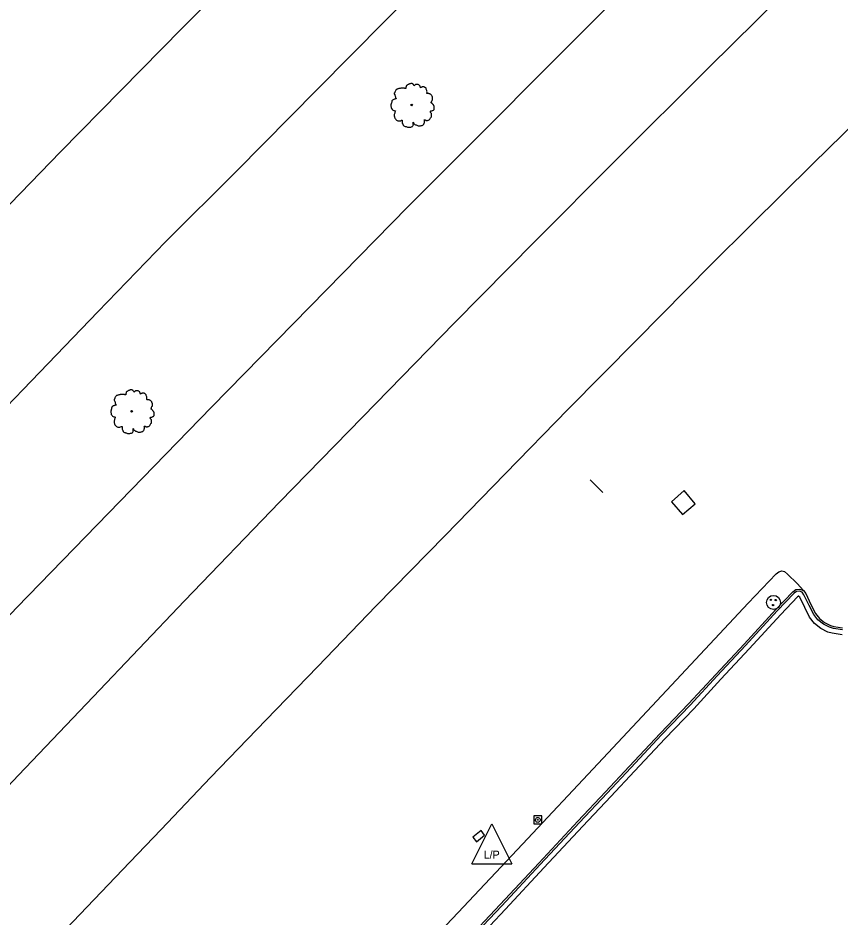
# Model space of a CAD drawing. Extents: x 2161152 to 2175754, y 602179 to 617749.
# Drawn here: x 2163328.7 to 2163534.2, y 605404.6 to 605629.5 of the extents above; entities that cross this region are included whole.
import ezdxf

# ---------------------------------------------------------------- set-up
doc = ezdxf.new("R2010")
doc.units = 0
for name, color, linetype in [('RD_EX_BldgApp_Sign', 7, 'Continuous'), ('RD_EX_Conc_Curb', 7, 'Continuous'), ('RD_EX_Conc_Gutter', 7, 'Continuous'), ('RD_EX_Conc_Sidewalk', 7, 'Continuous'), ('RD_EX_DR_Inlet', 7, 'Continuous'), ('RD_EX_Fence_Other', 7, 'Continuous'), ('RD_EX_Misc', 7, 'Continuous'), ('RD_EX_Road', 7, 'Continuous'), ('RD_EX_UT', 7, 'Continuous'), ('RD_EX_VEG', 7, 'Continuous')]:
    doc.layers.add(name, color=color, linetype=linetype)

msp = doc.modelspace()

# ---------------------------------------------------------------- linework, layer by layer
at = {"layer": 'RD_EX_BldgApp_Sign'}
msp.add_line((2163474.9, 605510.92), (2163471.74, 605514.08), dxfattribs=at)
at = {"layer": 'RD_EX_Conc_Curb'}
for points in [[(2163441.47, 605399.73), (2163449.26, 605408.02), (2163458.9, 605418.35), (2163468.67, 605428.78), (2163475.61, 605436.15), (2163481.51, 605442.46), (2163489.25, 605450.68), (2163496.34, 605458.1), (2163503.15, 605465.43), (2163510.21, 605473.01), (2163518.13, 605481.66), (2163522.37, 605486.12), (2163523.11, 605486.67), (2163524.12, 605486.79), (2163525.05, 605486.4), (2163525.61, 605485.65), (2163526.93, 605482.94), (2163528.04, 605480.71), (2163529.04, 605479.43), (2163530.31, 605478.41), (2163531.78, 605477.7), (2163532.64, 605477.45), (2163534.85, 605477.09)], [(2163534.81, 605476.59), (2163532.53, 605476.96), (2163531.6, 605477.23), (2163530.04, 605477.99), (2163528.69, 605479.08), (2163527.62, 605480.44), (2163526.48, 605482.72), (2163525.18, 605485.39), (2163524.73, 605485.99), (2163524.04, 605486.28), (2163523.3, 605486.19), (2163522.71, 605485.74), (2163518.5, 605481.32), (2163510.58, 605472.67), (2163503.51, 605465.09), (2163496.71, 605457.76), (2163489.61, 605450.34), (2163481.87, 605442.11), (2163475.97, 605435.81), (2163469.03, 605428.43), (2163459.27, 605418), (2163449.63, 605407.67), (2163441.84, 605399.39)]]:
    msp.add_lwpolyline(points, dxfattribs=at)
at = {"layer": 'RD_EX_Conc_Gutter'}
msp.add_lwpolyline([(2163534.71, 605475.34), (2163532.25, 605475.74), (2163531.15, 605476.06), (2163529.36, 605476.93), (2163527.79, 605478.2), (2163526.56, 605479.77), (2163525.36, 605482.17), (2163524.12, 605484.74), (2163523.94, 605484.97), (2163523.87, 605485), (2163523.78, 605484.99), (2163523.54, 605484.81), (2163519.41, 605480.47), (2163511.5, 605471.82), (2163504.43, 605464.24), (2163497.61, 605456.9), (2163490.52, 605449.48), (2163482.78, 605441.26), (2163476.88, 605434.96), (2163469.94, 605427.58), (2163460.18, 605417.15), (2163450.54, 605406.82), (2163442.74, 605398.53)], dxfattribs=at)
at = {"layer": 'RD_EX_Conc_Sidewalk'}
msp.add_lwpolyline([(2163420.93, 605387.17), (2163438.78, 605406.02), (2163454.8, 605423.09), (2163473.72, 605443.24), (2163492.04, 605462.78), (2163511.21, 605483.29), (2163518.23, 605490.6), (2163518.86, 605491.13), (2163519.66, 605491.32), (2163520.32, 605491.18), (2163521.05, 605490.54), (2163523.49, 605488.14), (2163524.34, 605487.29), (2163525.05, 605486.4)], dxfattribs=at)
at = {"layer": 'RD_EX_DR_Inlet'}
msp.add_lwpolyline([(2163492.1, 605508.61), (2163494.81, 605505.41), (2163498.02, 605508.12), (2163495.25, 605511.44), (2163492.1, 605508.61)], dxfattribs=at)
for centre, radius in [((2163517.56, 605483.46), 1.75), ((2163516.9, 605484.09), 0.175), ((2163517.48, 605482.8), 0.175), ((2163518.12, 605484.02), 0.175)]:
    msp.add_circle(centre, radius, dxfattribs=at)
at = {"layer": 'RD_EX_Fence_Other'}
msp.add_lwpolyline([(2162830.61, 604913.75), (2162883.17, 604978.53), (2162926.54, 605031.32), (2162974.34, 605088.61), (2163021.45, 605143.76), (2163066.11, 605195.56), (2163102.29, 605236.75), (2163137.02, 605275.59), (2163187.19, 605331.07), (2163243.16, 605391.37), (2163280.76, 605431.81), (2163328.44, 605482.21), (2163377.08, 605532.2), (2163426.27, 605582.33), (2163479.54, 605635.86), (2163514.27, 605670.47), (2163555.22, 605709.95), (2163593.34, 605746.66), (2163631.88, 605783.63), (2163692.53, 605840.5), (2163757.89, 605901.36), (2163814.91, 605953.51), (2163878.64, 606012.27)], dxfattribs=at)
at = {"layer": 'RD_EX_Misc'}
for points in [[(2163457.64, 605428.11), (2163459.64, 605428.11), (2163459.64, 605430.11), (2163457.64, 605430.11), (2163457.64, 605428.11)], [(2163458.04, 605429.11), (2163458.06, 605429.26), (2163458.12, 605429.41), (2163458.21, 605429.53), (2163458.33, 605429.62), (2163458.47, 605429.69), (2163458.62, 605429.71), (2163458.78, 605429.7), (2163458.92, 605429.64), (2163459.05, 605429.56), (2163459.15, 605429.44), (2163459.21, 605429.3), (2163459.24, 605429.15), (2163459.24, 605429.11)], [(2163459.24, 605429.11), (2163459.22, 605428.96), (2163459.17, 605428.82), (2163459.07, 605428.7), (2163458.95, 605428.6), (2163458.81, 605428.54), (2163458.66, 605428.51), (2163458.51, 605428.53), (2163458.36, 605428.58), (2163458.24, 605428.67), (2163458.14, 605428.79), (2163458.07, 605428.92), (2163458.04, 605429.07), (2163458.04, 605429.11)], [(2163458.54, 605429.11), (2163458.56, 605429.17), (2163458.61, 605429.21), (2163458.67, 605429.21), (2163458.72, 605429.17), (2163458.74, 605429.11)], [(2163458.74, 605429.11), (2163458.72, 605429.05), (2163458.67, 605429.02), (2163458.61, 605429.02), (2163458.56, 605429.05), (2163458.54, 605429.11)]]:
    msp.add_lwpolyline(points, dxfattribs=at)
at = {"layer": 'RD_EX_Road'}
for points in [[(2163192.72, 605390.99), (2163208.76, 605408.54), (2163230, 605431.6), (2163248.17, 605451.04), (2163266.02, 605469.94), (2163277.29, 605481.65), (2163294.54, 605499.67), (2163313.29, 605519.32), (2163330, 605536.69), (2163348.68, 605556.06), (2163365.58, 605573.53), (2163383.3, 605591.18), (2163403.47, 605611.59), (2163420.49, 605628.74), (2163437.33, 605645.83), (2163456.07, 605664.3), (2163473.56, 605681.76), (2163492.22, 605700.25), (2163508.44, 605716.16), (2163526.86, 605734.28), (2163544.44, 605751.28)], [(2163542.42, 605657.43), (2163525.09, 605640.48), (2163501.52, 605617.18), (2163478.04, 605593.83), (2163458, 605573.7), (2163437.84, 605553.28), (2163414.8, 605529.72), (2163394.11, 605508.54), (2163370.32, 605483.86), (2163347.47, 605459.89), (2163328.82, 605440.33), (2163309.38, 605419.82), (2163288.15, 605397.4)], [(2163384.88, 605642.22), (2163369.74, 605626.9), (2163354.45, 605611.35), (2163339.36, 605596.04), (2163319.15, 605575.31), (2163301.13, 605556.71), (2163281.24, 605536.02), (2163263, 605516.96), (2163243.11, 605495.97), (2163227.49, 605479.24), (2163208.59, 605459.01), (2163188.08, 605437.05), (2163169.08, 605416.74), (2163157.02, 605403.69)], [(2163332.54, 605393.28), (2163344.18, 605405.46), (2163356.65, 605418.52), (2163364.51, 605426.68), (2163376.85, 605439.68), (2163390.71, 605454.13), (2163403.57, 605467.39), (2163418.27, 605482.58), (2163435.46, 605500.2), (2163450.5, 605515.58), (2163466.2, 605531.73), (2163483.32, 605548.96), (2163502, 605567.91), (2163511.92, 605577.74), (2163527.46, 605593.1), (2163545.95, 605611.18)]]:
    msp.add_lwpolyline(points, dxfattribs=at)
at = {"layer": 'RD_EX_UT'}
for p, q in [((2163442.13, 605418.15), (2163447.13, 605428.15)), ((2163447.13, 605428.15), (2163452.13, 605418.15)), ((2163442.13, 605418.15), (2163452.13, 605418.15))]:
    msp.add_line(p, q, dxfattribs=at)
msp.add_lwpolyline([(2163442.42, 605424.79), (2163443.31, 605423.67), (2163445.36, 605425.32), (2163444.47, 605426.44), (2163442.42, 605424.79)], dxfattribs=at)
at = {"layer": 'RD_EX_VEG'}
for centre, radius in [((2163427.12, 605607.73), 0.188), ((2163427.11, 605607.72), 0.000075), ((2163357.11, 605531.21), 0.188), ((2163357.1, 605531.19), 0.000075)]:
    msp.add_circle(centre, radius, dxfattribs=at)
for points in [[(2163427.22, 605613.11), (2163426.99, 605613.13), (2163426.75, 605613.05), (2163426.56, 605612.98), (2163426.39, 605612.92), (2163426.22, 605612.84), (2163426, 605612.71), (2163425.83, 605612.56), (2163425.74, 605612.38), (2163425.7, 605612.21), (2163425.66, 605612), (2163425.66, 605611.87), (2163425.57, 605611.85), (2163425.45, 605611.87), (2163425.27, 605611.93), (2163425.08, 605611.93), (2163424.89, 605611.93), (2163424.63, 605611.91), (2163424.37, 605611.91), (2163424.16, 605611.87), (2163423.92, 605611.83), (2163423.64, 605611.74), (2163423.37, 605611.64), (2163423.15, 605611.46), (2163422.96, 605611.1), (2163422.87, 605610.84), (2163422.76, 605610.65), (2163422.87, 605610.31), (2163423, 605610.05), (2163423.02, 605609.9), (2163423.07, 605609.58), (2163423.15, 605609.41), (2163423.24, 605609.26), (2163423.19, 605609.25), (2163422.91, 605609.21), (2163422.68, 605609.13), (2163422.36, 605608.96), (2163422.19, 605608.8), (2163422.12, 605608.55), (2163422.1, 605608.29), (2163422.02, 605608.14), (2163421.97, 605607.93), (2163421.95, 605607.88), (2163421.91, 605607.63), (2163421.99, 605607.3), (2163422.01, 605607.03), (2163422.1, 605606.87), (2163422.21, 605606.73), (2163422.34, 605606.55), (2163422.64, 605606.38), (2163422.89, 605606.3), (2163423.04, 605606.28), (2163422.91, 605605.91), (2163422.87, 605605.65), (2163422.77, 605605.35), (2163422.77, 605605.29), (2163422.74, 605604.94), (2163422.85, 605604.69), (2163422.91, 605604.41), (2163423.04, 605604.24), (2163423.24, 605604.02), (2163423.49, 605603.85), (2163423.86, 605603.75), (2163424.16, 605603.77), (2163424.59, 605603.9), (2163424.78, 605603.96), (2163424.76, 605603.83), (2163424.78, 605603.55), (2163424.78, 605603.23), (2163424.89, 605602.99), (2163424.97, 605602.78), (2163425.08, 605602.59), (2163425.32, 605602.42), (2163425.62, 605602.37), (2163425.94, 605602.26), (2163426.28, 605602.2), (2163426.65, 605602.18), (2163427.1, 605602.29), (2163427.31, 605602.39), (2163427.39, 605602.52), (2163427.54, 605602.8), (2163427.5, 605602.97), (2163427.52, 605603.42), (2163427.59, 605603.29), (2163427.72, 605603.02), (2163428.1, 605602.8), (2163428.4, 605602.67), (2163428.75, 605602.55), (2163428.98, 605602.5), (2163429.33, 605602.55), (2163429.62, 605602.61), (2163429.9, 605602.7), (2163430.12, 605602.91), (2163430.25, 605603.12), (2163430.29, 605603.32), (2163430.35, 605603.6), (2163430.38, 605603.74)], [(2163430.38, 605603.74), (2163430.33, 605603.87), (2163430.29, 605604.05), (2163430.35, 605604.04), (2163430.48, 605604), (2163430.68, 605603.9), (2163430.85, 605603.85), (2163431.1, 605603.87), (2163431.3, 605603.94), (2163431.64, 605604.15), (2163431.85, 605604.5), (2163432.05, 605604.8), (2163432.11, 605605.05), (2163432.07, 605605.22), (2163432.05, 605605.59), (2163431.9, 605605.78), (2163431.86, 605605.87), (2163431.79, 605606.17), (2163431.85, 605606.21), (2163432.05, 605606.25), (2163432.33, 605606.34), (2163432.54, 605606.43), (2163432.71, 605606.57), (2163432.76, 605606.73), (2163432.75, 605607.03), (2163432.78, 605607.33), (2163432.73, 605607.45), (2163432.65, 605607.56), (2163432.6, 605607.71), (2163432.48, 605607.82), (2163432.41, 605607.93), (2163432.33, 605608.01), (2163432.24, 605608.12), (2163432.11, 605608.21), (2163432, 605608.25), (2163431.96, 605608.36), (2163432.07, 605608.51), (2163432.11, 605608.59), (2163432.13, 605608.76), (2163432.3, 605609.02), (2163432.33, 605609.32), (2163432.3, 605609.64), (2163432.26, 605609.85), (2163432.15, 605610.05), (2163432, 605610.24), (2163431.9, 605610.37), (2163431.77, 605610.46), (2163431.53, 605610.56), (2163431.34, 605610.6), (2163431.08, 605610.6), (2163430.93, 605610.63), (2163430.95, 605610.67), (2163430.95, 605610.78), (2163430.95, 605610.99), (2163430.89, 605611.33), (2163430.78, 605611.7), (2163430.78, 605611.72), (2163430.7, 605611.91), (2163430.53, 605612.06), (2163430.4, 605612.13), (2163430.25, 605612.23), (2163430.07, 605612.24), (2163429.84, 605612.24), (2163429.63, 605612.21), (2163429.48, 605612.13), (2163429.35, 605612.04), (2163429.3, 605612.15), (2163429.22, 605612.38), (2163429.18, 605612.49), (2163429.07, 605612.62), (2163428.9, 605612.77), (2163428.57, 605612.86), (2163428.1, 605612.81), (2163427.87, 605612.66), (2163427.76, 605612.53), (2163427.72, 605612.62), (2163427.57, 605612.77), (2163427.5, 605612.9), (2163427.37, 605612.99), (2163427.25, 605613.07), (2163427.18, 605613.11)], [(2163357.21, 605536.58), (2163356.98, 605536.6), (2163356.74, 605536.53), (2163356.55, 605536.45), (2163356.38, 605536.4), (2163356.21, 605536.32), (2163355.99, 605536.19), (2163355.82, 605536.04), (2163355.73, 605535.85), (2163355.69, 605535.68), (2163355.65, 605535.48), (2163355.65, 605535.35), (2163355.56, 605535.33), (2163355.45, 605535.35), (2163355.26, 605535.4), (2163355.07, 605535.4), (2163354.88, 605535.4), (2163354.62, 605535.38), (2163354.36, 605535.38), (2163354.15, 605535.35), (2163353.91, 605535.31), (2163353.63, 605535.21), (2163353.37, 605535.12), (2163353.14, 605534.93), (2163352.95, 605534.58), (2163352.86, 605534.31), (2163352.75, 605534.13), (2163352.86, 605533.79), (2163352.99, 605533.53), (2163353.01, 605533.38), (2163353.07, 605533.06), (2163353.14, 605532.89), (2163353.23, 605532.74), (2163353.18, 605532.72), (2163352.9, 605532.68), (2163352.67, 605532.61), (2163352.35, 605532.44), (2163352.18, 605532.27), (2163352.11, 605532.03), (2163352.09, 605531.77), (2163352.02, 605531.62), (2163351.96, 605531.41), (2163351.94, 605531.35), (2163351.9, 605531.11), (2163351.98, 605530.77), (2163352, 605530.51), (2163352.09, 605530.34), (2163352.2, 605530.21), (2163352.33, 605530.02), (2163352.63, 605529.85), (2163352.88, 605529.78), (2163353.03, 605529.76), (2163352.9, 605529.39), (2163352.86, 605529.12), (2163352.77, 605528.82), (2163352.77, 605528.77), (2163352.73, 605528.41), (2163352.84, 605528.17), (2163352.9, 605527.89), (2163353.03, 605527.72), (2163353.23, 605527.49), (2163353.48, 605527.32), (2163353.85, 605527.23), (2163354.15, 605527.25), (2163354.58, 605527.38), (2163354.77, 605527.44), (2163354.75, 605527.31), (2163354.77, 605527.02), (2163354.77, 605526.71), (2163354.88, 605526.46), (2163354.96, 605526.26), (2163355.07, 605526.07), (2163355.31, 605525.9), (2163355.61, 605525.84), (2163355.93, 605525.73), (2163356.27, 605525.67), (2163356.65, 605525.66), (2163357.1, 605525.77), (2163357.3, 605525.86), (2163357.38, 605525.99), (2163357.53, 605526.27), (2163357.49, 605526.44), (2163357.51, 605526.89), (2163357.58, 605526.76), (2163357.71, 605526.5), (2163358.09, 605526.27), (2163358.39, 605526.14), (2163358.74, 605526.03), (2163358.97, 605525.97), (2163359.33, 605526.03), (2163359.61, 605526.09), (2163359.89, 605526.18), (2163360.11, 605526.39), (2163360.24, 605526.59), (2163360.28, 605526.8), (2163360.34, 605527.08), (2163360.38, 605527.21)], [(2163360.38, 605527.21), (2163360.32, 605527.34), (2163360.28, 605527.53), (2163360.34, 605527.51), (2163360.47, 605527.47), (2163360.67, 605527.38), (2163360.84, 605527.32), (2163361.09, 605527.34), (2163361.29, 605527.42), (2163361.63, 605527.62), (2163361.84, 605527.98), (2163362.04, 605528.28), (2163362.1, 605528.52), (2163362.06, 605528.69), (2163362.04, 605529.07), (2163361.89, 605529.25), (2163361.86, 605529.35), (2163361.78, 605529.65), (2163361.84, 605529.69), (2163362.04, 605529.72), (2163362.32, 605529.82), (2163362.53, 605529.91), (2163362.7, 605530.04), (2163362.76, 605530.21), (2163362.74, 605530.51), (2163362.77, 605530.81), (2163362.72, 605530.92), (2163362.64, 605531.04), (2163362.59, 605531.19), (2163362.47, 605531.3), (2163362.4, 605531.41), (2163362.32, 605531.48), (2163362.23, 605531.6), (2163362.1, 605531.69), (2163361.99, 605531.73), (2163361.95, 605531.84), (2163362.06, 605531.99), (2163362.1, 605532.07), (2163362.12, 605532.23), (2163362.29, 605532.5), (2163362.32, 605532.8), (2163362.29, 605533.12), (2163362.25, 605533.32), (2163362.14, 605533.53), (2163361.99, 605533.72), (2163361.89, 605533.85), (2163361.76, 605533.94), (2163361.52, 605534.03), (2163361.33, 605534.07), (2163361.07, 605534.07), (2163360.92, 605534.11), (2163360.94, 605534.15), (2163360.94, 605534.26), (2163360.94, 605534.46), (2163360.88, 605534.8), (2163360.77, 605535.18), (2163360.77, 605535.2), (2163360.69, 605535.38), (2163360.53, 605535.53), (2163360.39, 605535.61), (2163360.24, 605535.7), (2163360.06, 605535.72), (2163359.83, 605535.72), (2163359.63, 605535.68), (2163359.48, 605535.61), (2163359.34, 605535.51), (2163359.29, 605535.63), (2163359.21, 605535.85), (2163359.18, 605535.96), (2163359.06, 605536.1), (2163358.89, 605536.25), (2163358.56, 605536.34), (2163358.09, 605536.28), (2163357.86, 605536.13), (2163357.75, 605536), (2163357.71, 605536.1), (2163357.56, 605536.25), (2163357.49, 605536.38), (2163357.36, 605536.47), (2163357.25, 605536.55), (2163357.17, 605536.58)]]:
    msp.add_spline(points, degree=3, dxfattribs=at)

# ---------------------------------------------------------------- texts
at = {"layer": 'RD_EX_UT'}
msp.add_text('L/P', height=2, dxfattribs=at).set_placement((2163445.12, 605419.43))

doc.saveas('drawing.dxf')
